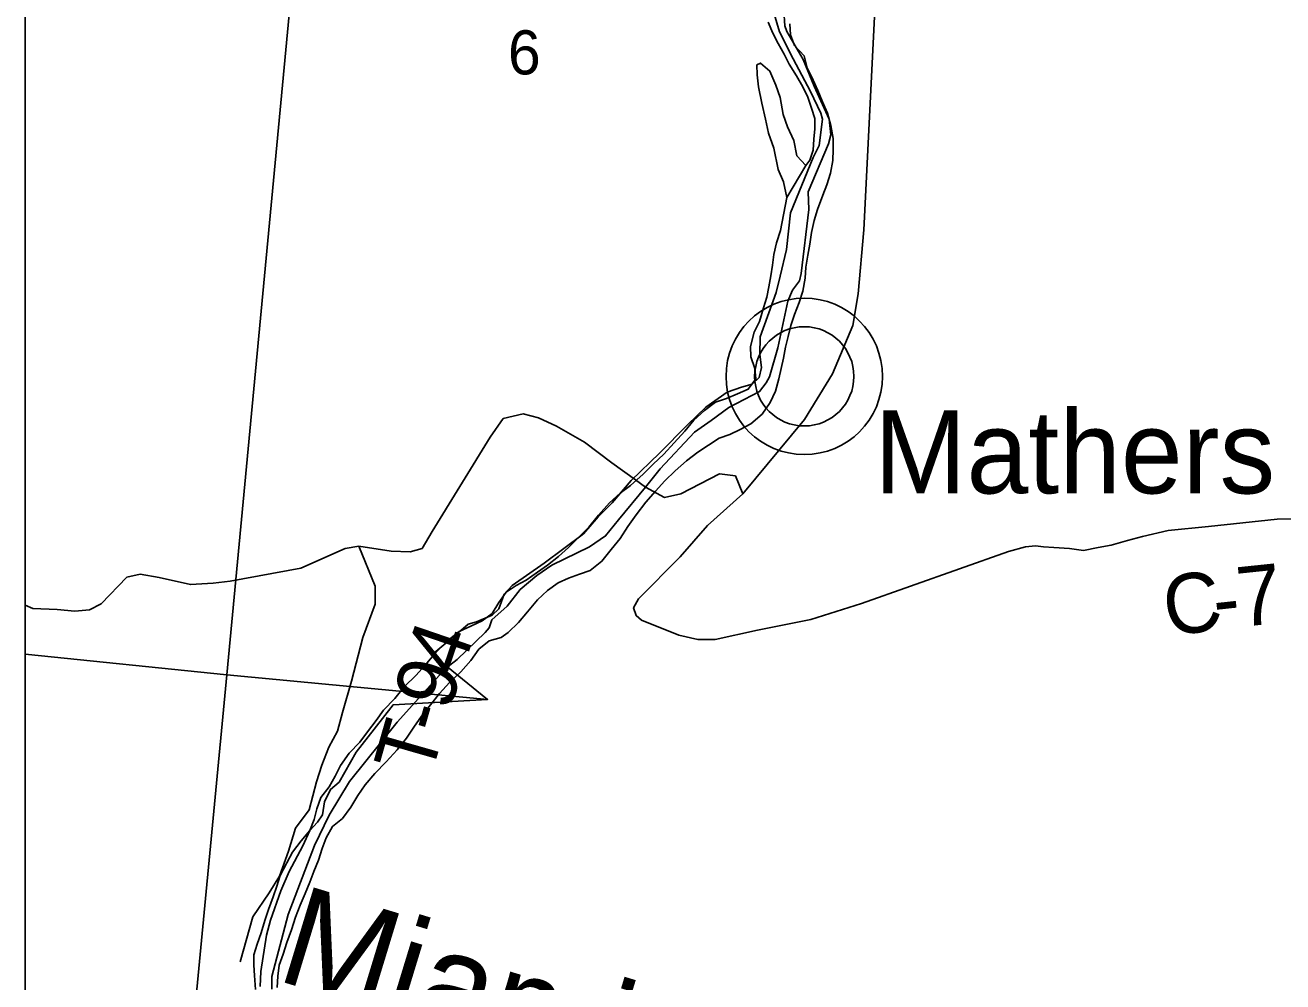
# Model space of a CAD drawing. Extents: x 0.4 to 34.4, y -2.1 to 19.9.
# Drawn here: x 3 to 4.197, y 14.193 to 15.102 of the extents above; entities that cross this region are included whole.
import ezdxf

# ---------------------------------------------------------------- set-up
doc = ezdxf.new("R2010")
doc.units = 0
for name, color, linetype in [('GM_X_County', 7, 'Continuous'), ('GM_X_County_Road', 7, 'Continuous'), ('GM_X_County_Road_Text', 7, 'Continuous'), ('GM_X_Major_River', 7, 'Continuous'), ('GM_X_Major_River_Text', 7, 'Continuous'), ('GM_X_Section', 7, 'Continuous'), ('GM_X_Section_Text', 7, 'Continuous'), ('GM_X_Township', 7, 'Continuous'), ('GM_X_Township_Road', 7, 'Continuous'), ('GM_X_Township_Road_Text', 7, 'Continuous'), ('GM_X_Unincorporated', 7, 'Continuous'), ('GM_X_Unincorporated_Text', 7, 'Continuous'), ('SH_Data', 7, 'Continuous')]:
    doc.layers.add(name, color=color, linetype=linetype)

msp = doc.modelspace()

# ---------------------------------------------------------------- linework, layer by layer
at = {"layer": 'GM_X_County'}
msp.add_lwpolyline([(9.8001, 15.3423), (9.8001, 18.8357), (3.0001, 18.8357), (3.0001, 12.0357), (9.5074, 12.0357)], dxfattribs=at)
at = {"layer": 'GM_X_County_Road'}
for points in [[(4.0921, 16.025), (4.075, 16.0392), (4.0559, 16.0588), (4.042, 16.007), (4.0308, 15.9623), (4.0179, 15.9268), (3.9392, 15.755), (3.8752, 15.6108), (3.8571, 15.559), (3.8445, 15.5155), (3.8329, 15.4647), (3.8225, 15.3954), (3.798, 14.9078), (3.7927, 14.8467), (3.7874, 14.8168), (3.7683, 14.7707), (3.7416, 14.7273), (3.683, 14.6568)], [(3.0001, 14.5507), (3.0074, 14.5478), (3.0306, 14.5467), (3.0475, 14.5452), (3.0613, 14.5465), (3.0724, 14.5521), (3.0967, 14.5773), (3.1094, 14.5802), (3.1275, 14.577), (3.1573, 14.5704), (3.1789, 14.5718), (3.195, 14.5736), (3.2624, 14.586), (3.3045, 14.6047), (3.3177, 14.6068), (3.3482, 14.6023), (3.3664, 14.6015), (3.3777, 14.6047), (3.3872, 14.621), (3.4424, 14.7106), (3.4549, 14.7284), (3.4739, 14.7327), (3.4886, 14.729), (3.5055, 14.7211), (3.5323, 14.7058), (3.5581, 14.6863), (3.5806, 14.6701)], [(3.5806, 14.6701), (3.5903, 14.6631), (3.6082, 14.6531), (3.624, 14.6568), (3.6606, 14.6758), (3.6758, 14.6739), (3.683, 14.6568)], [(3.683, 14.6568), (3.683, 14.6568), (3.6491, 14.6267), (3.6231, 14.5968), (3.5837, 14.5567), (3.5789, 14.5483), (3.5813, 14.5409), (3.5866, 14.5365), (3.6221, 14.5222), (3.64, 14.5183), (3.6566, 14.5183), (3.6967, 14.527), (3.7475, 14.5373), (3.7957, 14.5525), (3.9355, 14.6018), (3.9518, 14.6062), (3.9613, 14.6073), (3.969, 14.6062), (3.9787, 14.6055), (3.9935, 14.6047), (4.0069, 14.6029), (4.0208, 14.6055), (4.0332, 14.6078), (4.0488, 14.6123), (4.063, 14.616), (4.0875, 14.6218), (4.1259, 14.6257), (4.191, 14.6326), (4.2481, 14.634)]]:
    msp.add_lwpolyline(points, dxfattribs=at)
at = {"layer": 'GM_X_Major_River'}
msp.add_line((3.7246, 14.9385), (3.7429, 14.9689), dxfattribs=at)
for points in [[(3.4531, 14.52), (3.4597, 14.5249), (3.4693, 14.5343), (3.4779, 14.5444), (3.4875, 14.556), (3.4971, 14.5649), (3.5071, 14.572), (3.5171, 14.5764), (3.5274, 14.5804), (3.5377, 14.5837), (3.5488, 14.5926), (3.5577, 14.6038), (3.5662, 14.6143), (3.5736, 14.6256), (3.5814, 14.6368), (3.5907, 14.6488), (3.5999, 14.6593), (3.6088, 14.669), (3.6185, 14.6784), (3.6292, 14.6881), (3.64, 14.6962), (3.6503, 14.7029), (3.6603, 14.7096), (3.6706, 14.7132), (3.6802, 14.718), (3.6905, 14.7232), (3.7013, 14.7325), (3.709, 14.7434), (3.7138, 14.7543), (3.717, 14.766), (3.7194, 14.7758), (3.7215, 14.7856), (3.7235, 14.7962), (3.726, 14.8064), (3.7284, 14.8167), (3.732, 14.8272), (3.7363, 14.8385), (3.7399, 14.8495), (3.742, 14.8616), (3.7429, 14.8722), (3.7446, 14.8835), (3.7467, 14.8941), (3.7483, 14.9051), (3.7508, 14.9165), (3.754, 14.927), (3.7588, 14.9406), (3.7627, 14.9504), (3.7663, 14.9617), (3.7684, 14.9735), (3.7689, 14.9841), (3.7687, 14.9947), (3.7666, 15.0069), (3.7634, 15.0187), (3.7586, 15.0294), (3.7542, 15.0401), (3.7498, 15.05), (3.7439, 15.0619), (3.7411, 15.0733), (3.7321, 15.0829), (3.7281, 15.0932), (3.7275, 15.1035)], [(3.707, 15.1053), (3.7114, 15.0946), (3.7166, 15.085), (3.7221, 15.0747), (3.7269, 15.0652), (3.7339, 15.054), (3.7398, 15.0437), (3.7446, 15.0338), (3.7483, 15.0235), (3.7512, 15.0136), (3.7514, 15.0037), (3.7505, 14.9938), (3.7499, 14.9836), (3.7467, 14.9738), (3.7429, 14.9689)], [(3.7429, 14.9689), (3.7343, 14.9782), (3.7315, 14.9926), (3.7252, 15.0056), (3.7212, 15.0174), (3.7184, 15.0334), (3.7141, 15.0453), (3.7086, 15.0586), (3.6996, 15.0663), (3.6961, 15.0645), (3.6964, 15.055), (3.6977, 15.0436), (3.7009, 15.028), (3.7045, 15.0128), (3.7073, 14.9995), (3.7124, 14.9853), (3.7166, 14.9652), (3.7214, 14.9533), (3.7246, 14.9385)], [(3.7246, 14.9385), (3.7188, 14.9071), (3.7148, 14.8954), (3.7123, 14.8844), (3.7111, 14.8742), (3.7094, 14.864), (3.7077, 14.8534), (3.7056, 14.8436), (3.7025, 14.8337), (3.6988, 14.8205), (3.6937, 14.8104), (3.6901, 14.7968), (3.6904, 14.7869), (3.6944, 14.7758), (3.6953, 14.7659), (3.688, 14.7562), (3.6777, 14.7518), (3.6673, 14.7474), (3.657, 14.7438), (3.6463, 14.736), (3.6363, 14.7267), (3.6278, 14.7162), (3.6174, 14.7053), (3.6077, 14.6945), (3.5977, 14.6848), (3.588, 14.6754), (3.5761, 14.6646), (3.5661, 14.6572), (3.5561, 14.6482), (3.5457, 14.6363), (3.5364, 14.625), (3.5264, 14.6153), (3.5171, 14.6056), (3.5075, 14.597), (3.4971, 14.5888), (3.4875, 14.5822), (3.4768, 14.5747), (3.4672, 14.5696), (3.4576, 14.5633), (3.4507, 14.5535), (3.4444, 14.543), (3.4348, 14.5359), (3.4241, 14.5308), (3.413, 14.5257), (3.4023, 14.5171), (3.3907, 14.5059), (3.3807, 14.4939), (3.3718, 14.4838), (3.361, 14.4734), (3.3517, 14.4621), (3.3409, 14.4509), (3.3339, 14.4412), (3.3258, 14.4303), (3.3184, 14.4205), (3.3084, 14.4101), (3.3002, 14.3984), (3.2951, 14.3883), (3.2893, 14.3781), (3.2815, 14.368), (3.2776, 14.3571), (3.2751, 14.3469), (3.2708, 14.3367), (3.2627, 14.3266), (3.2546, 14.3161), (3.2491, 14.3059), (3.2428, 14.2939), (3.2396, 14.2837), (3.2361, 14.2735), (3.2317, 14.2614), (3.2281, 14.2509), (3.2245, 14.2392), (3.2209, 14.2286), (3.2177, 14.2184), (3.2176, 14.2086), (3.2182, 14.1987), (3.2191, 14.1854)], [(3.24, 14.1874), (3.2406, 14.198), (3.2419, 14.2086), (3.2455, 14.2191), (3.249, 14.2301), (3.2534, 14.2421), (3.2574, 14.2542), (3.2617, 14.2655), (3.2665, 14.2768), (3.2708, 14.2874), (3.2748, 14.2976), (3.2791, 14.3085), (3.2827, 14.3194), (3.2866, 14.3296), (3.2925, 14.3405), (3.3021, 14.348), (3.3099, 14.3588), (3.3165, 14.3697), (3.3235, 14.3799), (3.3328, 14.3907), (3.3436, 14.4019), (3.354, 14.4132), (3.3629, 14.4244), (3.3699, 14.4349), (3.3773, 14.4454), (3.3858, 14.4559), (3.3943, 14.4668), (3.4039, 14.4772), (3.4147, 14.4873), (3.424, 14.4982), (3.4318, 14.5091), (3.4414, 14.5169), (3.4531, 14.52)]]:
    msp.add_lwpolyline(points, dxfattribs=at)
at = {"layer": 'GM_X_Section'}
for p, q in [((3.0001, 15.5924), (3.0001, 14.5041)), ((3.0001, 14.5041), (3.0001, 13.5939))]:
    msp.add_line(p, q, dxfattribs=at)
for points in [[(3.0001, 14.5041), (3.192, 14.4845), (3.2941, 15.5661), (3.0001, 15.5924)], [(3.7069, 15.1326), (3.7176, 15.096), (3.7308, 15.0704), (3.7473, 15.0391), (3.7572, 15.0188), (3.7586, 15.0128), (3.7555, 14.9878), (3.7496, 14.9766), (3.7283, 14.9239), (3.7243, 14.8891), (3.7185, 14.8635), (3.7145, 14.848), (3.6993, 14.8059), (3.6991, 14.7892), (3.7007, 14.7767), (3.6983, 14.7673), (3.6918, 14.761), (3.6815, 14.7581), (3.6678, 14.7534), (3.6478, 14.739), (3.6301, 14.7223), (3.6035, 14.6955), (3.5766, 14.6694), (3.5584, 14.6481), (3.5453, 14.6347), (3.5314, 14.6187), (3.4938, 14.5909), (3.4635, 14.5695), (3.4558, 14.5613), (3.4506, 14.5474), (3.4445, 14.5414), (3.4296, 14.5349), (3.4216, 14.5327), (3.4058, 14.519), (3.3874, 14.5038), (3.44, 14.4612), (3.192, 14.4845), (3.2941, 15.5661)], [(3.0001, 13.5939), (3.106, 13.5839), (3.192, 14.4845), (3.0001, 14.5041)], [(3.106, 13.5839), (3.192, 14.4845), (3.44, 14.4612), (3.3502, 14.456), (3.332, 14.4328), (3.315, 14.4111), (3.2989, 14.3826), (3.2905, 14.3756), (3.285, 14.3639), (3.2829, 14.3515), (3.2782, 14.3444), (3.2709, 14.3365), (3.2642, 14.3219), (3.2513, 14.2975), (3.2434, 14.2791), (3.2334, 14.2512), (3.2298, 14.2369), (3.2242, 14.2025), (3.2236, 14.1882)]]:
    msp.add_lwpolyline(points, dxfattribs=at)
at = {"layer": 'GM_X_Township'}
msp.add_line((3.0001, 17.934), (3.0001, 12.5191), dxfattribs=at)
for points in [[(3.2349, 14.1856), (3.2347, 14.1976), (3.2503, 14.2566), (3.2754, 14.3224), (3.2893, 14.351), (3.3086, 14.3833), (3.3539, 14.4395), (3.4001, 14.4905), (3.411, 14.4991), (3.4378, 14.5249), (3.4414, 14.5293), (3.4441, 14.5369), (3.4588, 14.55), (3.4711, 14.5657), (3.487, 14.5791), (3.5011, 14.5887), (3.5369, 14.6063), (3.5523, 14.6166), (3.5645, 14.6321), (3.5903, 14.6631), (3.6043, 14.6803), (3.6368, 14.7152), (3.6526, 14.7264), (3.6694, 14.7389), (3.6988, 14.7539), (3.7051, 14.7621), (3.7082, 14.7679), (3.716, 14.7956), (3.7256, 14.8398), (3.7301, 14.8503), (3.7369, 14.8591), (3.7383, 14.8662), (3.7455, 14.9271), (3.745, 14.9439), (3.7642, 14.9894), (3.7665, 14.998), (3.7651, 15.0129), (3.7506, 15.0443), (3.7401, 15.0697), (3.7246, 15.0964), (3.7227, 15.1017), (3.7217, 15.1162)], [(3.7217, 15.1162), (3.7227, 15.1017), (3.7246, 15.0964), (3.7401, 15.0697), (3.7506, 15.0443), (3.7651, 15.0129), (3.7665, 14.998), (3.7642, 14.9894), (3.745, 14.9439), (3.7455, 14.9271), (3.7383, 14.8662), (3.7369, 14.8591), (3.7301, 14.8503), (3.7256, 14.8398), (3.716, 14.7956), (3.7082, 14.7679), (3.7051, 14.7621), (3.6988, 14.7539), (3.6694, 14.7389), (3.6526, 14.7264), (3.6368, 14.7152), (3.6043, 14.6803), (3.5903, 14.6631), (3.5645, 14.6321), (3.5523, 14.6166), (3.5369, 14.6063), (3.5011, 14.5887), (3.487, 14.5791), (3.4711, 14.5657), (3.4588, 14.55), (3.4441, 14.5369), (3.4414, 14.5293), (3.4378, 14.5249), (3.411, 14.4991), (3.4001, 14.4905), (3.3539, 14.4395), (3.3086, 14.3833), (3.2893, 14.351), (3.2754, 14.3224), (3.2503, 14.2566), (3.2347, 14.1976), (3.2349, 14.1856)]]:
    msp.add_lwpolyline(points, dxfattribs=at)
at = {"layer": 'GM_X_Township_Road'}
msp.add_lwpolyline([(3.3177, 14.6068), (3.3331, 14.569), (3.3332, 14.5519), (3.3215, 14.5202), (3.3107, 14.4786), (3.302, 14.4487), (3.2973, 14.4309), (3.2891, 14.4158), (3.2824, 14.3988), (3.2773, 14.3829), (3.2702, 14.3561), (3.2574, 14.3388), (3.2507, 14.3168), (3.2421, 14.293), (3.2324, 14.2772), (3.2166, 14.2546), (3.2047, 14.2118)], dxfattribs=at)
at = {"layer": 'GM_X_Unincorporated'}
for radius in [0.0744, 0.0472]:
    msp.add_circle((3.7413, 14.7684), radius, dxfattribs=at)
at = {"layer": 'SH_Data'}
msp.add_line((3.0001, 18.8357), (3.0001, 12.0357), dxfattribs=at)

# ---------------------------------------------------------------- texts
at = {"layer": 'GM_X_County_Road_Text'}
for s, rotation, p in [('7', 5.9747, (4.1558, 14.53)), ('C', 8.41, (4.0871, 14.5207)), ('-', 6.1704, (4.1327, 14.5275))]:
    msp.add_text(s, height=0.0568, rotation=rotation, dxfattribs=at).set_placement(p)
at = {"layer": 'GM_X_Major_River_Text'}
msp.add_text('Miami', height=0.09469, rotation=343.0376, dxfattribs=at).set_placement((3.2371, 14.1949))
at = {"layer": 'GM_X_Section_Text'}
msp.add_text('6', height=0.0419, rotation=0, dxfattribs=at).set_placement((3.4594, 15.0555))
at = {"layer": 'GM_X_Township_Road_Text'}
for s, rotation, p in [('4', 71.1125, (3.4139, 14.4818)), ('9', 73.2933, (3.404, 14.4489)), ('-', 73.8466, (3.3976, 14.4266)), ('T', 73.9781, (3.3859, 14.3858))]:
    msp.add_text(s, height=0.0568, rotation=rotation, dxfattribs=at).set_placement(p)
at = {"layer": 'GM_X_Unincorporated_Text'}
msp.add_text('Mathers Mills', height=0.078977, rotation=0, dxfattribs=at).set_placement((3.8077, 14.6571))

doc.saveas('drawing.dxf')
